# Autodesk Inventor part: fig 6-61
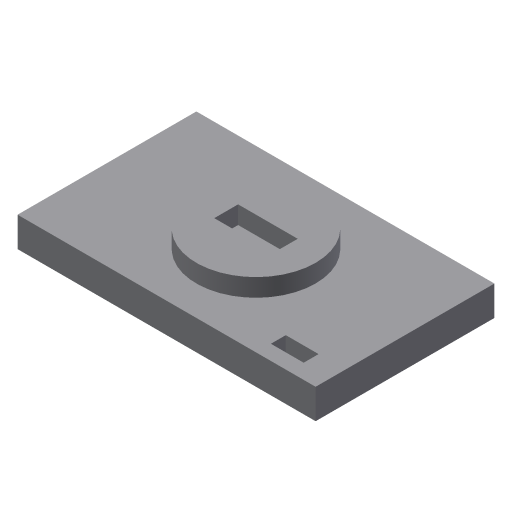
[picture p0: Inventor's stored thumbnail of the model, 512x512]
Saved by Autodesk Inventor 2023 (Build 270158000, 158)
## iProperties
Created: 2007-01
Part Number: fig 6-61
Document SubType Name: Modeling
Designer: Administrator
Density: 1 g/cm^3
Material: Generic
Appearance: Default
Author: Administrator
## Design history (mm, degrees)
sketch "Sketch1"
  geometry: L1 (-50, 30)-(50, 30); L2 (50, 30)-(50, -30); L3 (50, -30)-(-50, -30); L4 (-50, -30)-(-50, 30); 1 further point
  constraints: 8 end point, 2 parallel, 1 horizontal, 1 perpendicular, 1 other
  dimensions: "d0" = 50 distance from line of L4 point (0, 0); "d1" = 100 distance of L1.start L1.end; "d2" = 30 distance from line of L3 point (0, 0); "d3" = 60 distance between parallel lines of L3 L1
extrude "Extrusion1" new body sketch "Sketch1" distance "d4" = 10; taper "d5" = 0 deg
sketch "Sketch2"
  geometry: L1 (10, -4)-(-10, -4); L2 (-10, -4)-(-10, 4); L3 (-10, 4)-(10, 4); L4 (10, 4)-(10, -4); C1 r 20 at (0, 0); 1 further point
  constraints: 8 end point, 2 parallel, 1 centre point, 1 coincident, 1 horizontal, 1 perpendicular, 1 other
  dimensions: "d6" = 40 diameter of C1; "d7" = 4 distance from line of L3 point (0, 0); "d8" = 8 distance between parallel lines of L1 L3; "d9" = 10 distance from line of L2 point (0, 0); "d10" = 20 distance between parallel lines of L4 L2
extrude "Extrusion2" join sketch "Sketch2" distance "d11" = 6; taper "d12" = 0 deg
sketch "Sketch3"
  geometry: L1 (30, -20)-(41, -20); L2 (41, -20)-(41, -25); L3 (41, -25)-(30, -25); L4 (30, -25)-(30, -20)
  constraints: 8 end point, 2 parallel, 1 horizontal, 1 perpendicular
extrude "Extrusion3" cut sketch "Sketch3" extent not by distance; stored distance "d13" = 10; taper "d14" = 0 deg
body "Solid1"
